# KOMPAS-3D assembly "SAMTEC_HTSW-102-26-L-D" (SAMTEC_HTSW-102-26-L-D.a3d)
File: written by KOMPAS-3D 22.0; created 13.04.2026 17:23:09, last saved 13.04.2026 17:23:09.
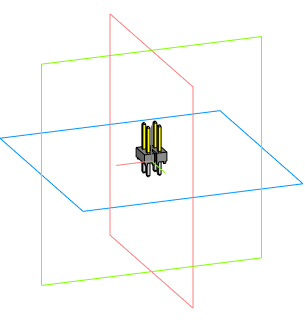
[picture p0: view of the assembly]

Document properties: Автор: Andrey; Полное имя файла: C:\Users\User1\Documents\SAMTEC_HTSW-102-26-L-D.a3d

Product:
- Component [assembly]: HTSW-102-23-L-D  | qty 1  | source file: HTSW-102-23-L-D.a3d
- Part/product: SAMTEC_HTSW-102-26-L-D
    Комментарий: SAMTEC_HTSW-102-26-L-D

Referenced files in C:\Users\User1\Documents\: HTSW-102-23-L-D.a3d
